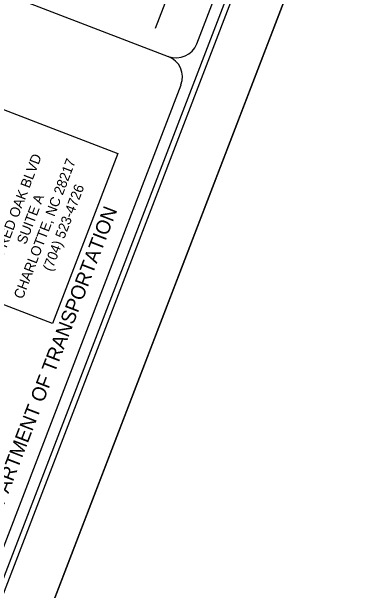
# Model space of a CAD drawing. Extents: x 1015221 to 1064345, y 619216 to 647967.
# Drawn here: x 1025328 to 1026604, y 637598 to 639697 of the extents above; entities that cross this region are included whole.
import ezdxf

# ---------------------------------------------------------------- set-up
doc = ezdxf.new("R2010")
doc.units = 0
for name, color, linetype in [('Old_Level_8', 7, 'Continuous'), ('Sheet Cutting Line CELL', 7, 'Continuous'), ('Sheet Data Text CELL', 7, 'Continuous'), ('Sheet Plot Border Inside CELL', 7, 'Continuous'), ('Sheet Plot Border Outside CELL', 7, 'Continuous'), ('Sheet Title CELL', 7, 'Continuous')]:
    doc.layers.add(name, color=color, linetype=linetype)

msp = doc.modelspace()

# ---------------------------------------------------------------- linework, layer by layer
at = {"layer": 'Sheet Cutting Line CELL'}
msp.add_line((1023435, 632235.3), (1028266.7, 644811.1), dxfattribs=at)
at = {"layer": 'Sheet Data Text CELL'}
msp.add_lwpolyline([(1024825.5, 638816.3), (1025062.2, 639432.5), (1025713.1, 639182.4), (1025476.4, 638566.2)], close=True, dxfattribs=at)
at = {"layer": 'Sheet Plot Border Inside CELL'}
msp.add_lwpolyline([(1023304.8, 632396.8), (1028086.2, 644841.8), (1020206.9, 647869.1), (1015425.5, 635424)], close=True, dxfattribs=at)
at = {"layer": 'Sheet Plot Border Outside CELL'}
msp.add_lwpolyline([(1020052.2, 647967.1), (1015220.5, 635391.3), (1023435, 632235.3), (1028266.7, 644811.1)], close=True, dxfattribs=at)
at = {"layer": 'Sheet Title CELL'}
for p, q in [((1026175.5, 640484.5), (1025849.1, 639635)), ((1024701.2, 639993.3), (1025896.4, 639534.1))]:
    msp.add_line(p, q, dxfattribs=at)
for points in [[(1023756.2, 633628.8), (1028002.6, 644681.1)], [(1025999.8, 639580.1), (1026817.6, 641708.4)], [(1024852.2, 636592.9), (1025942.5, 639430.7)]]:
    msp.add_lwpolyline(points, dxfattribs=at)
for centre, start, end in [((1025924.8, 639608.9), 248.983, 338.983), ((1025867.4, 639459.6), 338.983, 68.983)]:
    msp.add_arc(centre, 80, start, end, dxfattribs=at)

# ---------------------------------------------------------------- texts
at = {"layer": 'Old_Level_8'}
msp.add_text('FOR THE NORTH CAROLINA DEPARTMENT OF TRANSPORTATION', height=51.593, rotation=68.983, dxfattribs=at).set_placement((1024922, 636920.4))
at = {"layer": 'Sheet Data Text CELL'}
for s, height, p in [('8848 RED OAK BLVD', 36.237, (1025266.3, 638724.7)), ('CHARLOTTE, NC 28217', 36.237, (1025368.6, 638652)), ('(704) 523-4726', 36.237, (1025473.7, 638752.4)), ('SUITE A', 36.24, (1025379.6, 638850.2))]:
    msp.add_text(s, height=height, rotation=68.983, dxfattribs=at).set_placement(p)

doc.saveas('drawing.dxf')
